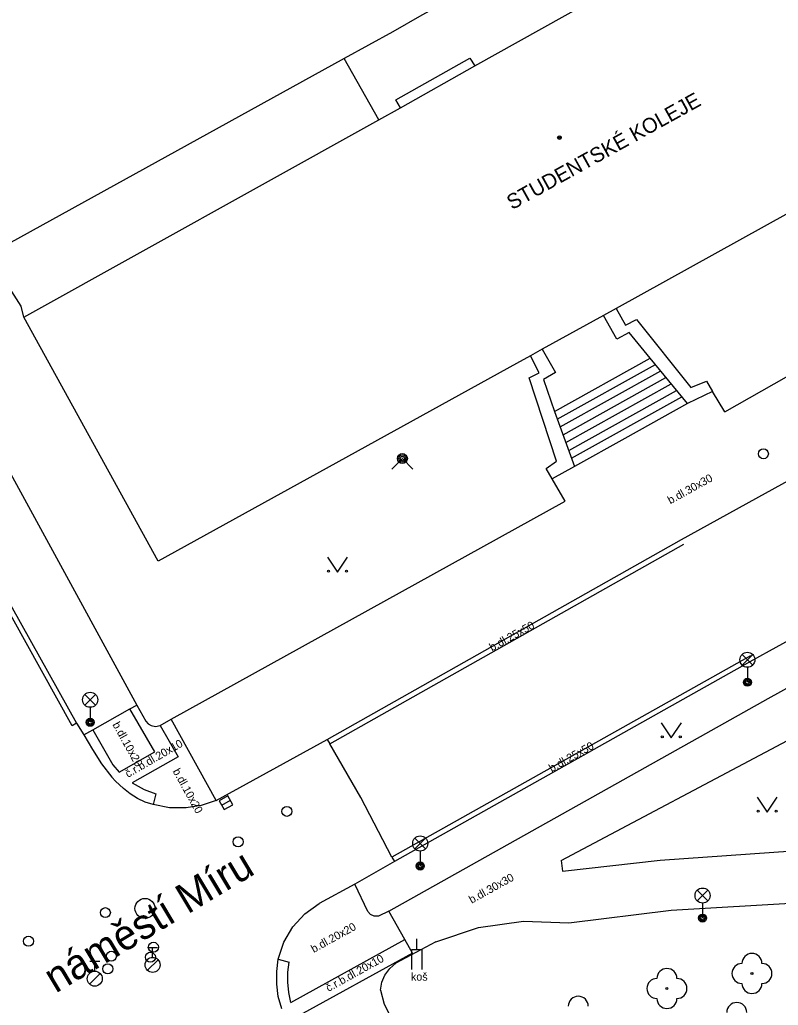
# Model space of a CAD drawing. Extents: x -600391 to -599491, y -1160176 to -1159402.
# Drawn here: x -600070.56 to -600032.66, y -1159783.53 to -1159734.28 of the extents above; entities that cross this region are included whole.
import ezdxf

# ---------------------------------------------------------------- set-up
doc = ezdxf.new("R2010")
doc.units = 0
for name, color, linetype in [('Level 10', 7, 'Continuous'), ('Level 11', 7, 'Continuous'), ('Level 22', 7, 'Continuous'), ('Level 27', 7, 'Continuous'), ('Level 28', 7, 'Continuous'), ('Level 31', 7, 'Continuous'), ('Level 33', 7, 'Continuous'), ('Level 36', 7, 'Continuous'), ('Level 38', 7, 'Continuous'), ('Level 39', 7, 'Continuous'), ('Level 40', 7, 'Continuous'), ('Level 41', 7, 'Continuous'), ('Level 42', 7, 'Continuous'), ('Level 5', 7, 'Continuous'), ('Level 50', 7, 'Continuous'), ('Level 7', 7, 'Continuous')]:
    doc.layers.add(name, color=color, linetype=linetype)

msp = doc.modelspace()

# ---------------------------------------------------------------- linework, layer by layer
at = {"layer": 'Level 10'}
for points in [[(-600055.19, -1159770.24), (-600037.5, -1159760.26), (-600024.42, -1159753.04), (-600019.11, -1159750.09), (-600018.94, -1159749.99), (-600018.24, -1159749.58), (-600014.95, -1159747.7), (-600014.1, -1159747.14), (-600013.48, -1159746.65), (-600013.31, -1159746.51), (-600012.1, -1159744.88), (-600011.64, -1159744.06), (-600011.31, -1159743.15), (-600010.96, -1159742.19), (-600010.3, -1159741.39), (-600009.52, -1159740.78), (-599987.04, -1159728.25), (-599984.89, -1159726.89), (-599984.19, -1159726.07)], [(-600084.35, -1159739.49), (-600078.84, -1159749.55), (-600067.73, -1159769.43)], [(-600022.44, -1159759.95), (-600033.92, -1159766.28), (-600051.83, -1159776.34)], [(-600067.73, -1159769.43), (-600067.35, -1159770.02)], [(-600067.35, -1159770.02), (-600066.93, -1159770.75), (-600066.47, -1159771.46), (-600065.96, -1159772.13)], [(-600060.75, -1159773.29), (-600055.19, -1159770.24)], [(-600065.96, -1159772.13), (-600065.78, -1159772.33), (-600065.58, -1159772.52), (-600065.38, -1159772.7)], [(-600063.9, -1159773.5), (-600064.29, -1159773.38), (-600064.68, -1159773.2), (-600065.04, -1159772.97), (-600065.38, -1159772.7)], [(-600060.75, -1159773.29), (-600061.5, -1159773.55), (-600062.24, -1159773.66), (-600063.07, -1159773.66), (-600063.9, -1159773.5)], [(-600051.83, -1159776.34), (-600053.82, -1159777.47)], [(-600053.82, -1159777.47), (-600055.6, -1159778.44)], [(-600057.65, -1159781.22), (-600057.37, -1159780.37), (-600056.92, -1159779.61), (-600056.32, -1159778.96), (-600055.6, -1159778.44)], [(-600057.47, -1159783.7), (-600057.64, -1159783.09), (-600057.72, -1159782.47), (-600057.72, -1159781.84), (-600057.65, -1159781.22)]]:
    msp.add_lwpolyline(points, dxfattribs=at)
at = {"layer": 'Level 11'}
for points in [[(-600043.95, -1159730.49), (-600050.47, -1159734.05), (-600051.91, -1159734.88), (-600054.34, -1159736.22)], [(-600054.34, -1159736.22), (-600072.13, -1159746.02)], [(-600052.61, -1159739.29), (-600054.34, -1159736.22)], [(-600051.53, -1159738.69), (-600047.82, -1159736.59)], [(-600070.35, -1159749.14), (-600070.48, -1159748.6), (-600072.13, -1159746.02), (-600072.8, -1159744.87)], [(-600035.32, -1159753.88), (-600020.65, -1159745.55)], [(-600075.95, -1159748.12), (-600074.51, -1159750.62), (-600074.05, -1159751.42), (-600064.71, -1159768.53)], [(-600067.73, -1159769.43), (-600067.94, -1159769.56), (-600076.99, -1159753.27), (-600079.06, -1159749.67)], [(-600043.84, -1159753.85), (-600039.06, -1159751.19)], [(-600043.7, -1159754.24), (-600038.79, -1159751.51)], [(-600043.56, -1159754.63), (-600038.53, -1159751.83)], [(-600043.41, -1159755.02), (-600038.27, -1159752.15)], [(-600043.27, -1159755.41), (-600038, -1159752.47)], [(-600043.13, -1159755.8), (-600037.74, -1159752.8)], [(-600042.99, -1159756.19), (-600037.47, -1159753.12)], [(-600035.32, -1159753.88), (-600035.94, -1159752.85)], [(-600037.19, -1159753.46), (-600040.32, -1159755.2), (-600042.84, -1159756.6)], [(-600063, -1159769.24), (-600043.3, -1159758.34), (-600043.95, -1159757.23)], [(-600055.19, -1159770.24), (-600055.07, -1159770.46), (-600037.37, -1159760.48)], [(-600033.16, -1159768.2), (-600030.33, -1159766.64), (-600019.7, -1159760.8)], [(-600034.04, -1159766.06), (-600051.96, -1159776.13), (-600051.83, -1159776.34)], [(-600043.5, -1159776.3), (-600043.43, -1159776.83), (-600038.55, -1159776.27), (-600030.74, -1159775.72), (-600023.74, -1159775.81), (-600023.57, -1159775.47), (-600027.89, -1159767.81)], [(-600043.5, -1159776.3), (-600032.192, -1159770.302), (-600031.11, -1159769.7), (-600030.67, -1159770.49), (-600029.05, -1159769.56), (-600029.46, -1159768.71), (-600027.89, -1159767.81)], [(-600052.11, -1159778.82), (-600036.27, -1159769.95), (-600033.16, -1159768.2)], [(-600066.9, -1159769.76), (-600065.91, -1159771.52), (-600065.59, -1159771.88), (-600063.81, -1159770.86), (-600065.05, -1159768.72)], [(-600066.9, -1159769.76), (-600065.05, -1159768.72)], [(-600065.05, -1159768.72), (-600064.71, -1159768.53)], [(-600064.71, -1159768.53), (-600064.26, -1159769.34), (-600064.14, -1159769.47), (-600064, -1159769.55), (-600063.77, -1159769.6), (-600063.54, -1159769.55)], [(-600063.54, -1159769.55), (-600063, -1159769.24)], [(-600060.75, -1159773.29), (-600063, -1159769.24)], [(-600067.35, -1159770.02), (-600066.9, -1159769.76)], [(-600063.54, -1159769.55), (-600062.64, -1159771.11), (-600064.94, -1159772.42), (-600064.35, -1159772.75), (-600063.76, -1159772.97), (-600063.9, -1159773.5)], [(-600051.96, -1159776.13), (-600053.52, -1159773.15), (-600055.07, -1159770.46)], [(-600053.17, -1159778.85), (-600053.82, -1159777.47)], [(-600043.13, -1159779.41), (-600038.01, -1159778.77), (-600031.48, -1159778.39), (-600027.46, -1159778.27), (-600025.46, -1159778.33), (-600025.01, -1159779.18), (-600026.63, -1159783.05), (-600030.24, -1159793.84), (-600038.89, -1159790.39)], [(-600052.11, -1159778.82), (-600052.64, -1159779.08), (-600052.85, -1159779.08), (-600053.03, -1159779), (-600053.17, -1159778.85)], [(-600051.31, -1159780.24), (-600052.11, -1159778.82)], [(-600049.77, -1159780.36), (-600047.63, -1159779.65), (-600045.39, -1159779.33), (-600043.13, -1159779.41)], [(-600057.01, -1159783.39), (-600051.31, -1159780.24)], [(-600050.94, -1159780.93), (-600051.31, -1159780.24)], [(-600049.77, -1159780.36), (-600051.76, -1159781.43)], [(-600057.65, -1159781.22), (-600057.1, -1159781.37)], [(-600050.94, -1159780.93), (-600056.74, -1159784.13)], [(-600057.01, -1159783.39), (-600057.12, -1159782.89), (-600057.17, -1159782.38), (-600057.16, -1159781.88), (-600057.1, -1159781.37)], [(-600052.54, -1159782.78), (-600052.46, -1159782.38), (-600052.31, -1159782.02), (-600052.07, -1159781.69)], [(-600051.76, -1159781.43), (-600052.07, -1159781.69)], [(-600052.54, -1159782.78), (-600052.35, -1159783.48)], [(-600052.35, -1159783.48), (-600052.02, -1159784.13)]]:
    msp.add_lwpolyline(points, dxfattribs=at)
at = {"layer": 'Level 22'}
for centre in [(-600033.97, -1159781.94), (-600038.22, -1159782.69)]:
    msp.add_circle(centre, 0.05, dxfattribs=at)
for centre, start, end in [((-600033.97, -1159781.44), 0, 180), ((-600038.22, -1159782.19), 0, 180), ((-600034.47, -1159781.94), 90, 270), ((-600033.47, -1159781.94), 270, 90), ((-600038.72, -1159782.69), 90, 270), ((-600037.72, -1159782.69), 270, 90), ((-600033.97, -1159782.44), 180, 0), ((-600042.65, -1159783.58), 0, 180), ((-600038.22, -1159783.19), 180, 0), ((-600034.73, -1159783.89), 0, 180)]:
    msp.add_arc(centre, 0.5, start, end, dxfattribs=at)
at = {"layer": 'Level 27'}
msp.add_line((-600060.468, -1159773.533), (-600060.032, -1159773.287), dxfattribs=at)
msp.add_lwpolyline([(-600060.345, -1159773.751), (-600059.909, -1159773.505), (-600060.155, -1159773.069), (-600060.591, -1159773.315)], close=True, dxfattribs=at)
msp.add_circle((-600064.3, -1159778.69), 0.5, dxfattribs=at)
at = {"layer": 'Level 28'}
for p, q in [((-600064.17, -1159780.635), (-600063.67, -1159780.635)), ((-600063.92, -1159781.135), (-600063.92, -1159780.635)), ((-600067.06, -1159781.325), (-600066.56, -1159781.325)), ((-600066.81, -1159781.825), (-600066.81, -1159781.325)), ((-600064.178, -1159781.782), (-600063.648, -1159781.252)), ((-600067.068, -1159782.472), (-600066.538, -1159781.942))]:
    msp.add_line(p, q, dxfattribs=at)
for centre, radius in [((-600033.4, -1159755.97), 0.25), ((-600063.88, -1159780.63), 0.25), ((-600065.98, -1159781.08), 0.25), ((-600063.92, -1159781.51), 0.375), ((-600064.03, -1159781.13), 0.25), ((-600066.16, -1159781.71), 0.25), ((-600066.81, -1159782.2), 0.375)]:
    msp.add_circle(centre, radius, dxfattribs=at)
at = {"layer": 'Level 31'}
msp.add_lwpolyline([(-600051.97, -1159756.74), (-600051.44, -1159756.21), (-600050.91, -1159756.74)], dxfattribs=at)
for centre, radius in [((-600051.44, -1159756.21), 0.25), ((-600051.44, -1159756.21), 0.18), ((-600051.44, -1159756.21), 0.11), ((-600057.21, -1159773.84), 0.25), ((-600059.65, -1159775.36), 0.25), ((-600066.28, -1159778.9), 0.25), ((-600070.12, -1159780.33), 0.25)]:
    msp.add_circle(centre, radius, dxfattribs=at)
at = {"layer": 'Level 33'}
for p, q in [((-600034.465, -1159766.53), (-600033.935, -1159766)), ((-600034.465, -1159766), (-600033.935, -1159766.53)), ((-600034.2, -1159766.64), (-600034.2, -1159767.39)), ((-600067.305, -1159768.53), (-600066.775, -1159768)), ((-600067.305, -1159768), (-600066.775, -1159768.53)), ((-600067.04, -1159768.64), (-600067.04, -1159769.39)), ((-600050.815, -1159775.71), (-600050.285, -1159775.18)), ((-600050.815, -1159775.18), (-600050.285, -1159775.71)), ((-600050.55, -1159775.82), (-600050.55, -1159776.57)), ((-600036.705, -1159778.31), (-600036.175, -1159777.78)), ((-600036.705, -1159777.78), (-600036.175, -1159778.31)), ((-600036.44, -1159778.42), (-600036.44, -1159779.17))]:
    msp.add_line(p, q, dxfattribs=at)
for centre, radius in [((-600034.2, -1159766.265), 0.375), ((-600034.2, -1159767.39), 0.2), ((-600034.2, -1159767.39), 0.145), ((-600034.2, -1159767.39), 0.0876), ((-600067.04, -1159768.265), 0.375), ((-600067.04, -1159769.39), 0.2), ((-600067.04, -1159769.39), 0.145), ((-600067.04, -1159769.39), 0.0876), ((-600050.55, -1159775.445), 0.375), ((-600050.55, -1159776.57), 0.2), ((-600050.55, -1159776.57), 0.145), ((-600050.55, -1159776.57), 0.0876), ((-600036.44, -1159778.045), 0.375), ((-600036.44, -1159779.17), 0.2), ((-600036.44, -1159779.17), 0.145), ((-600036.44, -1159779.17), 0.0876)]:
    msp.add_circle(centre, radius, dxfattribs=at)
at = {"layer": 'Level 36'}
for points in [[(-600055.18, -1159761.13), (-600054.68, -1159761.88), (-600054.18, -1159761.13)], [(-600038.5, -1159769.42), (-600038, -1159770.17), (-600037.5, -1159769.42)], [(-600033.71, -1159773.13), (-600033.21, -1159773.88), (-600032.71, -1159773.13)]]:
    msp.add_lwpolyline(points, dxfattribs=at)
for centre in [(-600055.13, -1159761.83), (-600054.231, -1159761.83), (-600038.45, -1159770.12), (-600037.551, -1159770.12), (-600033.66, -1159773.83), (-600032.761, -1159773.83)]:
    msp.add_circle(centre, 0.05, dxfattribs=at)
at = {"layer": 'Level 38'}
msp.add_line((-600050.71, -1159780.74), (-600050.71, -1159780.21), dxfattribs=at)
msp.add_lwpolyline([(-600050.96, -1159781.74), (-600050.96, -1159780.74), (-600050.46, -1159780.74), (-600050.46, -1159781.74)], dxfattribs=at)
at = {"layer": 'Level 39'}
for radius in [0.09, 0.0398]:
    msp.add_circle((-600043.59, -1159740.17), radius, dxfattribs=at)
at = {"layer": 'Level 5'}
for points in [[(-600047.82, -1159736.59), (-600042.29, -1159733.51)], [(-600051.77, -1159738.28), (-600048.07, -1159736.2)], [(-600048.07, -1159736.2), (-600047.82, -1159736.59)], [(-600051.53, -1159738.69), (-600051.77, -1159738.28)], [(-600022.11, -1159738.38), (-600040.75, -1159748.71)], [(-600052.61, -1159739.29), (-600051.53, -1159738.69)], [(-600070.35, -1159749.14), (-600052.61, -1159739.29)], [(-600040.75, -1159748.71), (-600041.39, -1159749.06)], [(-600063.64, -1159761.34), (-600070.35, -1159749.14)], [(-600041.39, -1159749.06), (-600044.45, -1159750.75)], [(-600045.04, -1159751.07), (-600045.74, -1159751.46)], [(-600044.45, -1159750.75), (-600045.04, -1159751.07)], [(-600045.74, -1159751.46), (-600063.64, -1159761.34)]]:
    msp.add_lwpolyline(points, dxfattribs=at)
at = {"layer": 'Level 7'}
for points in [[(-600040.75, -1159748.71), (-600040.29, -1159749.54), (-600039.74, -1159749.26), (-600037.02, -1159752.66), (-600036.25, -1159752.34), (-600035.94, -1159752.85)], [(-600039.06, -1159751.19), (-600040.11, -1159749.91), (-600040.73, -1159750.25), (-600041.39, -1159749.06)], [(-600043.95, -1159757.23), (-600044.25, -1159756.71), (-600043.74, -1159756.34), (-600045.1, -1159752.18), (-600044.6, -1159751.93), (-600045.04, -1159751.07)], [(-600044.45, -1159750.75), (-600043.79, -1159751.9), (-600044.39, -1159752.25), (-600043.84, -1159753.85)], [(-600037.19, -1159753.46), (-600039.06, -1159751.19)], [(-600035.94, -1159752.85), (-600037.19, -1159753.46)], [(-600043.84, -1159753.85), (-600042.84, -1159756.6)], [(-600042.84, -1159756.6), (-600043.95, -1159757.23)]]:
    msp.add_lwpolyline(points, dxfattribs=at)

# ---------------------------------------------------------------- texts
at = {"layer": 'Level 40'}
for s, height, rotation, p in [('b.dl.30x30', 0.4, 29, (-600038.05, -1159758.5)), ('b.dl.25x50', 0.4, 28.8292, (-600046.96, -1159765.85)), ('b.dl.10x20', 0.4, 299, (-600065.94, -1159769.5)), ('č.r.b.dl.20x10', 0.39999, 30, (-600065.15, -1159772.17)), ('b.dl.25x50', 0.4, 29.2854, (-600043.98, -1159771.89)), ('b.dl.10x20', 0.4, 299, (-600062.93, -1159771.83)), ('b.dl.30x30', 0.4, 29, (-600047.98, -1159778.46)), ('b.dl.20x20', 0.4, 29, (-600055.87, -1159780.92)), ('č.r.b.dl.20x10', 0.39999, 29, (-600055.13, -1159782.87))]:
    msp.add_text(s, height=height, rotation=rotation, dxfattribs=at).set_placement(p)
at = {"layer": 'Level 41'}
msp.add_text('STUDENTSKÉ KOLEJE', height=0.75, rotation=29, dxfattribs=at).set_placement((-600045.96, -1159743.8))
at = {"layer": 'Level 42'}
msp.add_text('koš', height=0.4, dxfattribs=at).set_placement((-600051.01, -1159782.3))
at = {"layer": 'Level 50'}
msp.add_text('náměstí Míru', height=1.5, rotation=30.9418, dxfattribs=at).set_placement((-600068.769, -1159782.952))
msp.add_text('náměstí Míru', height=1.5, rotation=30.9418, dxfattribs=at).set_placement((-600068.769, -1159782.952))

doc.saveas('drawing.dxf')
